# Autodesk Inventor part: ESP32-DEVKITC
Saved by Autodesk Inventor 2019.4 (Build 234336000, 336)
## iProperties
Created: 2020-03
Part Number: ESP32-DEVKITC
Material: Generic
Document SubType Name: Modeling
Designer: Administrator
Density: 1 g/cm^3
Appearance: Default
Title: MODULE_ESP32-DEVKITC
Author: Administrator
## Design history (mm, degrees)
feature "MODULE_ESP32-DEVKITC"
body "Solid1"
